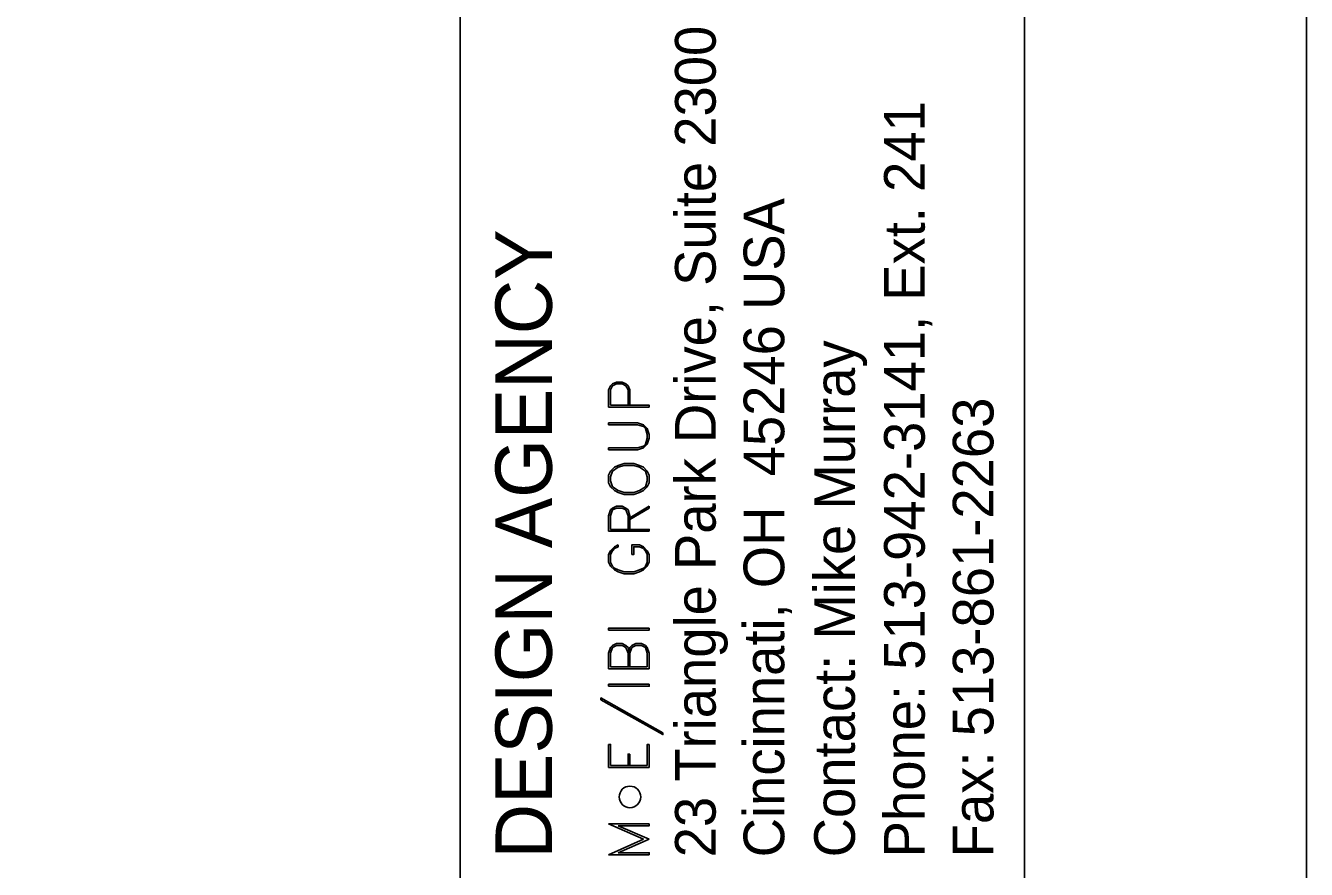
# Model space of a CAD drawing. Extents: x -2063 to 2068, y 79 to 1202.
# Drawn here: x -452.55 to -441.2, y 338.49 to 345.97 of the extents above; entities that cross this region are included whole.
import ezdxf

# ---------------------------------------------------------------- set-up
doc = ezdxf.new("R2010")
doc.units = 0
for name, color, linetype in [('SH_Border', 7, 'Continuous'), ('SH_Cut_Line', 7, 'Continuous'), ('SH_Data', 7, 'Continuous')]:
    doc.layers.add(name, color=color, linetype=linetype)

msp = doc.modelspace()

# ---------------------------------------------------------------- linework, layer by layer
at = {"layer": 'SH_Border'}
msp.add_line((-448.702, 244.968), (-448.702, 349.968), dxfattribs=at)
msp.add_lwpolyline([(-601.202, 349.968), (-443.702, 349.968), (-443.702, 244.968), (-601.202, 244.968)], close=True, dxfattribs=at)
at = {"layer": 'SH_Cut_Line'}
msp.add_lwpolyline([(-611.202, 352.468), (-441.202, 352.468), (-441.202, 242.468), (-611.202, 242.468)], close=True, dxfattribs=at)
at = {"layer": 'SH_Data'}
for p, q in [((-447.387, 342.585), (-447.027, 342.585)), ((-447.198, 341.606), (-447.027, 341.709)), ((-447.387, 341.486), (-447.027, 341.486)), ((-447.387, 340.267), (-447.027, 340.267)), ((-447.37, 340.285), (-447.044, 340.285)), ((-447.387, 339.392), (-447.387, 339.598)), ((-447.027, 339.392), (-447.027, 339.598)), ((-447.198, 339.409), (-447.198, 339.512)), ((-447.387, 339.392), (-447.027, 339.392)), ((-447.37, 339.409), (-447.044, 339.409)), ((-447.387, 338.894), (-447.078, 338.757)), ((-447.387, 338.894), (-447.027, 338.894)), ((-447.301, 338.877), (-447.027, 338.757)), ((-447.387, 338.62), (-447.078, 338.757)), ((-447.301, 338.637), (-447.027, 338.757)), ((-447.387, 338.62), (-447.027, 338.62))]:
    msp.add_line(p, q, dxfattribs=at)
for points in [[(-447.387, 342.585), (-447.387, 342.739), (-447.37, 342.774), (-447.353, 342.791), (-447.318, 342.808), (-447.267, 342.808), (-447.233, 342.791), (-447.215, 342.774), (-447.198, 342.739), (-447.198, 342.602)], [(-447.37, 342.602), (-447.37, 342.739), (-447.353, 342.774), (-447.318, 342.791), (-447.267, 342.791), (-447.233, 342.774), (-447.215, 342.739), (-447.215, 342.602)], [(-447.37, 342.602), (-447.027, 342.602), (-447.027, 342.585)], [(-447.387, 342.207), (-447.13, 342.207), (-447.078, 342.224), (-447.044, 342.259), (-447.027, 342.31), (-447.027, 342.344), (-447.044, 342.396), (-447.078, 342.43), (-447.13, 342.447), (-447.387, 342.447)], [(-447.387, 342.207), (-447.387, 342.224), (-447.13, 342.224), (-447.078, 342.241), (-447.061, 342.259), (-447.044, 342.31), (-447.044, 342.344), (-447.061, 342.396), (-447.078, 342.413), (-447.13, 342.43), (-447.387, 342.43), (-447.387, 342.447)], [(-447.387, 341.915), (-447.37, 341.881), (-447.336, 341.847), (-447.301, 341.829), (-447.25, 341.812), (-447.164, 341.812), (-447.112, 341.829), (-447.078, 341.847), (-447.044, 341.881), (-447.027, 341.915), (-447.027, 341.984), (-447.044, 342.018), (-447.078, 342.053), (-447.112, 342.07), (-447.164, 342.087), (-447.25, 342.087), (-447.301, 342.07), (-447.336, 342.053), (-447.37, 342.018), (-447.387, 341.984), (-447.387, 341.915)], [(-447.37, 341.932), (-447.353, 341.881), (-447.301, 341.847), (-447.25, 341.829), (-447.164, 341.829), (-447.112, 341.847), (-447.061, 341.881), (-447.044, 341.932), (-447.044, 341.967), (-447.061, 342.018), (-447.112, 342.053), (-447.164, 342.07), (-447.25, 342.07), (-447.301, 342.053), (-447.353, 342.018), (-447.37, 341.967), (-447.37, 341.932)], [(-447.387, 341.486), (-447.387, 341.623), (-447.37, 341.675), (-447.353, 341.692), (-447.318, 341.709), (-447.267, 341.709), (-447.233, 341.692), (-447.215, 341.675), (-447.198, 341.623), (-447.198, 341.503)], [(-447.198, 341.589), (-447.027, 341.692), (-447.027, 341.709)], [(-447.37, 341.503), (-447.37, 341.623), (-447.353, 341.675), (-447.318, 341.692), (-447.267, 341.692), (-447.233, 341.675), (-447.215, 341.623), (-447.215, 341.503)], [(-447.37, 341.503), (-447.027, 341.503), (-447.027, 341.486)], [(-447.301, 341.366), (-447.336, 341.349), (-447.37, 341.314), (-447.387, 341.28), (-447.387, 341.211), (-447.37, 341.177), (-447.336, 341.143), (-447.301, 341.126), (-447.25, 341.108), (-447.164, 341.108), (-447.112, 341.126), (-447.078, 341.143), (-447.044, 341.177), (-447.027, 341.211), (-447.027, 341.28), (-447.044, 341.314), (-447.078, 341.349), (-447.112, 341.366), (-447.181, 341.366), (-447.181, 341.28)], [(-447.301, 341.366), (-447.301, 341.349), (-447.336, 341.332), (-447.353, 341.314), (-447.37, 341.28), (-447.37, 341.211), (-447.353, 341.177), (-447.336, 341.16), (-447.301, 341.143), (-447.25, 341.126), (-447.164, 341.126), (-447.112, 341.143), (-447.078, 341.16), (-447.061, 341.177), (-447.044, 341.211), (-447.044, 341.28), (-447.061, 341.314), (-447.078, 341.332), (-447.112, 341.349), (-447.164, 341.349), (-447.164, 341.28), (-447.181, 341.28)], [(-447.387, 340.611), (-447.027, 340.611), (-447.027, 340.628)], [(-447.387, 340.611), (-447.387, 340.628), (-447.027, 340.628)], [(-447.387, 340.267), (-447.387, 340.405), (-447.37, 340.456), (-447.353, 340.473), (-447.318, 340.491), (-447.267, 340.491), (-447.233, 340.473), (-447.215, 340.456), (-447.198, 340.405)], [(-447.37, 340.285), (-447.37, 340.405), (-447.353, 340.456), (-447.318, 340.473), (-447.267, 340.473), (-447.233, 340.456), (-447.215, 340.405)], [(-447.215, 340.285), (-447.215, 340.405), (-447.198, 340.456), (-447.181, 340.473), (-447.147, 340.491), (-447.095, 340.491), (-447.061, 340.473), (-447.044, 340.456), (-447.027, 340.405), (-447.027, 340.267)], [(-447.198, 340.285), (-447.198, 340.405), (-447.181, 340.456), (-447.147, 340.473), (-447.095, 340.473), (-447.061, 340.456), (-447.044, 340.405), (-447.044, 340.285)], [(-447.387, 340.113), (-447.027, 340.113), (-447.027, 340.13)], [(-447.387, 340.113), (-447.387, 340.13), (-447.027, 340.13)], [(-447.456, 339.993), (-447.456, 340.01), (-446.906, 339.701)], [(-447.456, 339.993), (-446.906, 339.684), (-446.906, 339.701)], [(-447.37, 339.409), (-447.37, 339.598), (-447.387, 339.598)], [(-447.044, 339.409), (-447.044, 339.598), (-447.027, 339.598)], [(-447.215, 339.409), (-447.215, 339.512), (-447.198, 339.512)], [(-447.301, 338.877), (-447.027, 338.877), (-447.027, 338.894)], [(-447.301, 338.637), (-447.027, 338.637), (-447.027, 338.62)]]:
    msp.add_lwpolyline(points, dxfattribs=at)
msp.add_circle((-447.198, 339.132), 0.0956, dxfattribs=at)

# ---------------------------------------------------------------- texts
for s, height, p in [('23 Triangle Park Drive, Suite 2300', 0.36047, (-446.438, 338.597)), ('Phone: 513-942-3141, Ext. 241', 0.36047, (-444.585, 338.597)), ('Cincinnati, OH  45246 USA', 0.36047, (-445.83, 338.597)), ('DESIGN AGENCY', 0.50001, (-447.89, 338.587)), ('Contact: Mike Murray', 0.36047, (-445.204, 338.597)), ('Fax: 513-861-2263', 0.36047, (-443.976, 338.597))]:
    msp.add_text(s, height=height, rotation=90, dxfattribs=at).set_placement(p)

doc.saveas('drawing.dxf')
